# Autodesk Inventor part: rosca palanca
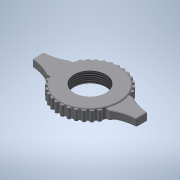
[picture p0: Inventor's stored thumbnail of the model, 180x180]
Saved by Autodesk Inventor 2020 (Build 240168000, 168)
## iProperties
Created: 2018-10
Part Number: rosca palanca
Material: Genérico
Document SubType Name: Modeling
Designer: Pedro
Density: 1 g/cm^3
Appearance: Por defecto
Author: Pedro
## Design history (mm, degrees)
sketch "Boceto1"
  geometry: L1 (-42.5, 0)-(-42.5, 4.5); L2 (-22.583, 9.5)-(-25.807, 9.5); L3 (42.5, 0)-(42.5, 4.5); L4 (22.583, 9.5)-(25.807, 9.5); L5 (-42.5, 0)-(-42.5, -4.5); L6 (-22.583, -9.5)-(-25.807, -9.5); L7 (0, -13)-(0, -24.5); L8 (42.5, 0)-(42.5, -4.5); L9 (22.583, -9.5)-(25.807, -9.5); A1 r 36.654 centre (-44.369, 41.106) between (-42.5, 4.5) and (-25.807, 9.5); A2 r 36.654 centre (44.369, 41.106) between (25.807, 9.5) and (42.5, 4.5); A3 r 36.654 centre (-44.369, -41.106) between (-25.807, -9.5) and (-42.5, -4.5); A4 r 36.654 centre (44.369, -41.106) between (42.5, -4.5) and (25.807, -9.5); A5 r 1.5 centre (2.333, 24.488) between (3.805, 24.203) and (0.833, 24.486); A6 r 1.5 centre (6.793, 23.643) between (8.188, 23.091) and (5.318, 23.916); A7 r 1.5 centre (11.021, 21.992) between (12.291, 21.194) and (9.622, 22.532); A8 r 1.5 centre (14.875, 19.592) between (15.976, 18.574) and (13.598, 20.38); A9 r 1.5 centre (20.948, 12.896) between (21.607, 11.549) and (20.042, 14.091); A10 r 1.5 centre (18.222, 16.526) between (19.117, 15.322) and (17.111, 17.534); A11 r 1.5 centre (-2.207, 24.5) between (-0.707, 24.49) and (-3.681, 24.222); A12 r 1.5 centre (-6.671, 23.677) between (-5.195, 23.943) and (-8.069, 23.133); A13 r 1.5 centre (-10.908, 22.048) between (-9.506, 22.581) and (-12.182, 21.257); A14 r 1.5 centre (-14.774, 19.669) between (-13.493, 20.45) and (-15.881, 18.656); A15 r 1.5 centre (-18.136, 16.619) between (-17.021, 17.622) and (-19.038, 15.421); A16 r 1.5 centre (-20.881, 13.004) between (-19.969, 14.194) and (-21.548, 11.66); A17 r 1.5 centre (-20.948, -12.896) between (-21.607, -11.549) and (-20.042, -14.091); A18 r 1.5 centre (-18.222, -16.526) between (-19.117, -15.322) and (-17.111, -17.534); A19 r 1.5 centre (-14.875, -19.592) between (-15.976, -18.574) and (-13.598, -20.38); A20 r 1.5 centre (-11.021, -21.992) between (-12.291, -21.194) and (-9.622, -22.532); A21 r 1.5 centre (-6.793, -23.643) between (-8.188, -23.091) and (-5.318, -23.916); A22 r 1.5 centre (-2.333, -24.488) between (-3.805, -24.203) and (-0.833, -24.486); A23 r 1.5 centre (2.207, -24.5) between (0.707, -24.49) and (3.681, -24.222); A24 r 1.5 centre (6.671, -23.677) between (5.195, -23.943) and (8.069, -23.133); A25 r 1.5 centre (10.908, -22.048) between (9.506, -22.581) and (12.182, -21.257); A26 r 1.5 centre (14.774, -19.669) between (13.493, -20.45) and (15.881, -18.656); A27 r 1.5 centre (18.136, -16.619) between (17.021, -17.622) and (19.038, -15.421); A28 r 1.5 centre (20.881, -13.004) between (19.969, -14.194) and (21.548, -11.66); A29 r 24.5 centre (0, 0) between (20.042, 14.091) and (19.117, 15.322); A30 r 24.5 centre (0, 0) between (17.111, 17.534) and (15.976, 18.574); A31 r 24.5 centre (0, 0) between (13.598, 20.38) and (12.291, 21.194); A32 r 24.5 centre (0, 0) between (9.622, 22.532) and (8.188, 23.091); A33 r 24.5 centre (0, 0) between (5.318, 23.916) and (3.805, 24.203); A34 r 24.5 centre (0, 0) between (0.833, 24.486) and (-0.707, 24.49); A35 r 24.5 centre (0, 0) between (-3.681, 24.222) and (-5.195, 23.943); A36 r 24.5 centre (0, 0) between (-8.069, 23.133) and (-9.506, 22.581); A37 r 24.5 centre (0, 0) between (-12.182, 21.257) and (-13.493, 20.45); A38 r 24.5 centre (0, 0) between (-15.881, 18.656) and (-17.021, 17.622); A39 r 24.5 centre (0, 0) between (-19.038, 15.421) and (-19.969, 14.194); A40 r 24.5 centre (0, 0) between (-20.042, -14.091) and (-19.117, -15.322); A41 r 24.5 centre (0, 0) between (-17.111, -17.534) and (-15.976, -18.574); A42 r 24.5 centre (0, 0) between (-13.598, -20.38) and (-12.291, -21.194); A43 r 24.5 centre (0, 0) between (-9.622, -22.532) and (-8.188, -23.091); A44 r 24.5 centre (0, 0) between (-5.318, -23.916) and (-3.805, -24.203); A45 r 24.5 centre (0, 0) between (-0.833, -24.486) and (0.707, -24.49); A46 r 24.5 centre (0, 0) between (3.681, -24.222) and (5.195, -23.943); A47 r 24.5 centre (0, 0) between (8.069, -23.133) and (9.506, -22.581); A48 r 24.5 centre (0, 0) between (12.182, -21.257) and (13.493, -20.45); A49 r 24.5 centre (0, 0) between (15.881, -18.656) and (17.021, -17.622); A50 r 24.5 centre (0, 0) between (19.038, -15.421) and (19.969, -14.194); A51 r 24.5 centre (0, 0) between (21.548, -11.66) and (22.583, -9.5); A52 r 24.5 centre (0, 0) between (22.583, 9.5) and (21.607, 11.549); A53 r 24.5 centre (0, 0) between (-21.548, 11.66) and (-22.583, 9.5); A54 r 24.5 centre (0, 0) between (-22.583, -9.5) and (-21.607, -11.549); 3 further points
  constraints: 109 point on circle, 54 centre point, 18 end point, 2 coincident, 1 vertical alignment, 2 other
extrude "Extrusión1" new body sketch "Boceto1" distance "d32" = 8; taper "d33" = 0 deg
sketch "Boceto2"
  geometry: C1 r 13 at (0, 0) reference; C2 r 24.5 at (0, 0); A1 r 24.5 centre (0, 0) between (22.583, 9.5) and (21.607, 11.549) reference; A2 r 24.5 centre (0, 0) between (-21.548, 11.66) and (-22.583, 9.5) reference
  constraints: 1 centre point, 1 coincident, 1 concentric
extrude "Extrusión2" join sketch "Boceto2" distance "d34" = 1; taper "d35" = 0 deg
fillet "Empalme1" dims "d36" = 1
sketch "Boceto3"
  geometry: C1 r 16.5 at (0, 0); C2 r 21.5 at (0, 0); A1 r 24.5 centre (0, 0) between (21.607, -11.549) and (22.583, -9.5) reference
  constraints: 2 centre point, 2 coincident
  dimensions: "d37" = 33 diameter of C1; "d38" = 43 diameter of C2
extrude "Extrusión3" cut sketch "Boceto3" distance "d39" = 5; taper "d40" = 0 deg
fillet "Empalme2" dims "d41" = 1
fillet "Empalme3" dims "d42" = 1
feature "Rosca1" dims "d43" = 10, "d44" = 0
feature "Rosca2" dims "d45" = 10, "d46" = 0
sketch "Boceto4"
  geometry: L1 (2.954, 0)-(0, 0) reference; L2 (-16.963, 0)-(-16.963, 7) reference; L3 (2.954, 0)-(-16.963, 0); L4 (-16.963, 0)-(-16.963, 6); L5 (2.954, 0)-(2.954, 7) reference; L6 (-16.963, 6)-(2.954, 0); L7 (48.12, 0)-(48.12, 7) reference; L8 (68.037, 0)-(67.113, 0) reference; L9 (48.12, 0)-(68.037, 0); L10 (68.037, 0)-(68.037, 6); L11 (68.037, 7)-(68.037, 0) reference; L12 (68.037, 6)-(48.12, 0); 3 further points
  constraints: 12 end point, 2 horizontal, 2 point on line
  dimensions: "d48" = 6 distance of L2.start L4.end; "d49" = 6 distance of L8.start L10.end
extrude "Extrusión4" cut sketch "Boceto4" distance "d50" = 19; taper "d51" = 0 deg
node "Plano de trabajo1"
sketch "Boceto5"
  geometry: L1 (-42.5, 3.562)-(-42.5, -3.562); L2 (-26.037, -9.366)-(-26.037, -7.076); L3 (-26.037, 7.076)-(-26.037, 9.366); L4 (-40.5, -2.646)-(-40.5, 2.646); L5 (42.5, -3.562)-(42.5, 3.562); L6 (26.037, 7.076)-(26.037, 9.366); L7 (26.037, -9.366)-(26.037, -7.076); L8 (40.5, -2.646)-(40.5, 2.646); C1 r 13 at (0, 0) reference; A1 r 36.654 centre (-44.369, -41.106) between (-26.037, -9.366) and (-41.576, -4.559); A2 r 38.654 centre (-44.369, -41.106) between (-26.037, -7.076) and (-40.5, -2.646); A3 r 1 centre (-41.5, -3.562) between (-42.5, -3.562) and (-41.576, -4.559); A4 r 36.654 centre (-44.369, 41.106) between (-41.576, 4.559) and (-26.037, 9.366); A5 r 1 centre (-41.5, 3.562) between (-41.576, 4.559) and (-42.5, 3.562); A6 r 38.654 centre (-44.369, 41.106) between (-40.5, 2.646) and (-26.037, 7.076); A7 r 36.654 centre (44.369, 41.106) between (26.037, 9.366) and (41.576, 4.559); A8 r 1 centre (41.5, -3.562) between (41.576, -4.559) and (42.5, -3.562); A9 r 1 centre (41.5, 3.562) between (42.5, 3.562) and (41.576, 4.559); A10 r 36.654 centre (44.369, -41.106) between (41.576, -4.559) and (26.037, -9.366); A11 r 38.654 centre (44.369, 41.106) between (26.037, 7.076) and (40.5, 2.646); A12 r 38.654 centre (44.369, -41.106) between (40.5, -2.646) and (26.037, -7.076)
  constraints: 25 point on circle, 16 end point, 12 centre point, 8 tangent, 2 equal radius, 1 vertical
extrude "Extrusión5" join sketch "Boceto5" distance "d57" = 4; taper "d58" = 0 deg
node "Sólido1"
other parameters: "d3" = 55, "d52" = -6
